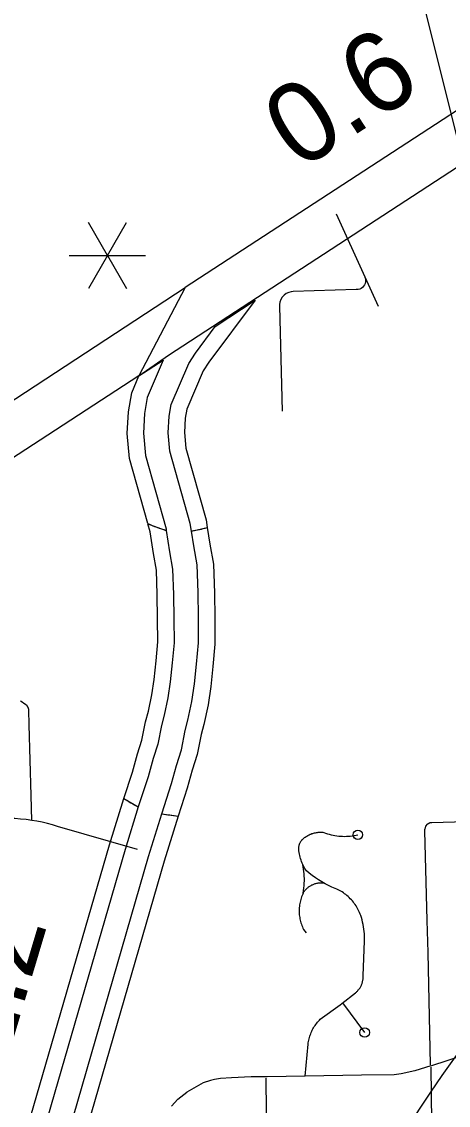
# Model space of a CAD drawing. Extents: x 309348 to 309445, y 336383 to 336484.
# Drawn here: x 309351.067 to 309351.516, y 336400.194 to 336401.336 of the extents above; entities that cross this region are included whole.
import ezdxf

# ---------------------------------------------------------------- set-up
doc = ezdxf.new("R2010")
doc.units = 0
doc.layers.add('R_Annotation', color=7, linetype='Continuous')

msp = doc.modelspace()

# ---------------------------------------------------------------- linework, layer by layer
at = {"layer": 'R_Annotation'}
for p, q in [((309351.1568, 336401.0896), (309351.1368, 336401.1242)), ((309351.1568, 336401.0896), (309351.1768, 336401.1242)), ((309351.1167, 336401.0896), (309351.1568, 336401.0896)), ((309351.1568, 336401.0896), (309351.1368, 336401.0549)), ((309351.1568, 336401.0896), (309351.1968, 336401.0896)), ((309351.1568, 336401.0896), (309351.1768, 336401.0549)), ((309351.2704, 336401.0147), (309351.3123, 336401.0426)), ((309351.1901, 336400.9626), (309351.2157, 336400.9791))]:
    msp.add_line(p, q, dxfattribs=at)
for points in [[(309351.7151, 336400.4543), (309351.2446, 336402.3368), (309349.4843, 336402.3368)], [(309353.5386, 336401.9502), (309353.1512, 336401.9259), (309352.6374, 336401.8975), (309352.6056, 336401.8933), (309352.5814, 336401.8881), (309352.5234, 336401.871), (309352.4797, 336401.8556), (309352.4295, 336401.8304), (309352.3881, 336401.8076), (309352.305, 336401.7552), (309352.2745, 336401.7342), (309351.6382, 336401.3162), (309351.2388, 336401.0557)], [(309351.2388, 336401.0557), (309351.1901, 336400.9626), (309351.2211, 336400.9844), (309351.6656, 336401.2744), (309352.3024, 336401.6927), (309352.3325, 336401.7134), (309352.4136, 336401.7645), (309352.4527, 336401.7861), (309352.4993, 336401.8094), (309352.5388, 336401.8234), (309352.5938, 336401.8396), (309352.6141, 336401.844), (309352.642, 336401.8477), (309353.1541, 336401.876), (309353.5417, 336401.9003)], [(309351.3978, 336401.1334), (309351.4278, 336401.067), (309351.428, 336401.0665), (309351.4285, 336401.0649), (309351.4286, 336401.0632), (309351.4285, 336401.0616), (309351.4281, 336401.06), (309351.4275, 336401.0585), (309351.4265, 336401.0571), (309351.4254, 336401.0559), (309351.4241, 336401.0549), (309351.4226, 336401.0542), (309351.421, 336401.0538), (309351.4194, 336401.0536), (309351.4188, 336401.0536), (309351.3525, 336401.0515), (309351.3505, 336401.0513), (309351.3478, 336401.0506), (309351.3452, 336401.0494), (309351.3429, 336401.0477), (309351.341, 336401.0456), (309351.3395, 336401.0432), (309351.3385, 336401.0405), (309351.3381, 336401.0377), (309351.338, 336401.0362), (309351.341, 336400.9255)], [(309351.4278, 336401.067), (309351.4418, 336401.0361)], [(309350.7477, 336400.7347), (309350.7689, 336400.7494), (309350.7971, 336400.7662), (309351.2388, 336401.0557), (309351.1901, 336400.9626)], [(309351.3123, 336401.0426), (309351.2635, 336400.9771), (309351.2577, 336400.9679), (309351.2404, 336400.9276), (309351.2387, 336400.9181), (309351.238, 336400.9029), (309351.2394, 336400.8864), (309351.2607, 336400.8108), (309351.262, 336400.8027)], [(309351.2453, 336400.7991), (309351.244, 336400.8072), (309351.2226, 336400.8833), (309351.2209, 336400.9026), (309351.2218, 336400.92), (309351.224, 336400.9325), (309351.2426, 336400.9758), (309351.2495, 336400.9867), (309351.2704, 336401.0147)], [(309351.2157, 336400.9791), (309351.1989, 336400.94), (309351.1959, 336400.9229), (309351.1948, 336400.9021), (309351.197, 336400.8786), (309351.2186, 336400.8015), (309351.2189, 336400.7998)], [(309351.1901, 336400.9626), (309350.8236, 336400.7238), (309350.796, 336400.7073), (309350.7757, 336400.6932)], [(309351.1994, 336400.8069), (309351.1802, 336400.8755), (309351.1778, 336400.9018), (309351.179, 336400.9248), (309351.1825, 336400.9449), (309351.1901, 336400.9626)], [(309351.1742, 336400.5173), (309351.1832, 336400.5448), (309351.1884, 336400.5641), (309351.1932, 336400.5788), (309351.197, 336400.598), (309351.2, 336400.6092), (309351.2036, 336400.6264), (309351.206, 336400.6426), (309351.2081, 336400.6622), (309351.21, 336400.6822), (309351.2097, 336400.7067), (309351.2094, 336400.7323), (309351.2085, 336400.7579), (309351.2053, 336400.7753), (309351.2019, 336400.7981), (309351.1995, 336400.8068)], [(309351.1995, 336400.8068), (309351.2052, 336400.8045), (309351.2189, 336400.7998)], [(309351.2189, 336400.7998), (309351.2223, 336400.7772), (309351.2255, 336400.7589), (309351.2265, 336400.7321), (309351.2268, 336400.7064), (309351.2271, 336400.6811), (309351.2251, 336400.6602), (309351.2231, 336400.6402), (309351.2205, 336400.6232), (309351.2167, 336400.6051), (309351.2138, 336400.5941), (309351.2099, 336400.5744), (309351.2049, 336400.5592), (309351.1997, 336400.5401), (309351.1893, 336400.5085)], [(309351.2142, 336400.5011), (309351.2243, 336400.5331), (309351.2295, 336400.5521), (309351.2348, 336400.5683), (309351.2388, 336400.5888), (309351.2417, 336400.5996), (309351.2459, 336400.6193), (309351.2486, 336400.6379), (309351.2508, 336400.6587), (309351.2529, 336400.6813), (309351.2526, 336400.7082), (309351.2523, 336400.7343), (309351.2512, 336400.7636), (309351.2477, 336400.7836), (309351.2453, 336400.7991)], [(309351.262, 336400.8027), (309351.2646, 336400.7851), (309351.2684, 336400.7643), (309351.2695, 336400.7337), (309351.2698, 336400.7075), (309351.2701, 336400.6798), (309351.2679, 336400.6563), (309351.2657, 336400.6351), (309351.2628, 336400.6158), (309351.2584, 336400.5952), (309351.2556, 336400.5845), (309351.2515, 336400.5636), (309351.246, 336400.5469), (309351.2409, 336400.528), (309351.2313, 336400.4986)], [(309351.2453, 336400.7991), (309351.262, 336400.8027)], [(309351.0773, 336400.4941), (309351.0765, 336400.5202), (309351.0746, 336400.5949), (309351.0741, 336400.6104), (309351.0741, 336400.6106), (309351.0741, 336400.6108), (309351.0741, 336400.611), (309351.074, 336400.6113), (309351.074, 336400.6115), (309351.0739, 336400.6117), (309351.0739, 336400.6119), (309351.0738, 336400.6121), (309351.0738, 336400.6123), (309351.0737, 336400.6125), (309351.0736, 336400.6127), (309351.0735, 336400.6129), (309351.0734, 336400.6131), (309351.0733, 336400.6133), (309351.0732, 336400.6135), (309351.0731, 336400.6137), (309351.073, 336400.6139), (309351.0728, 336400.6141), (309351.0727, 336400.6142), (309351.0726, 336400.6144), (309351.0724, 336400.6146), (309351.0723, 336400.6147), (309351.0706, 336400.6161), (309351.0688, 336400.6174), (309351.0671, 336400.6186), (309351.0653, 336400.6198)], [(309351.0727, 336399.4543), (309351.0557, 336399.4536), (309351.0515, 336399.4801), (309351.0657, 336399.5912), (309351.071, 336399.6624), (309351.0712, 336399.7171), (309351.0703, 336399.7842), (309351.0603, 336399.9436), (309351.0576, 336400.0443), (309351.0601, 336400.0883), (309351.0645, 336400.1326), (309351.0701, 336400.1608), (309351.1591, 336400.4684), (309351.1742, 336400.5173), (309351.1893, 336400.5085)], [(309351.1893, 336400.5085), (309351.1754, 336400.4635), (309351.0867, 336400.1568), (309351.0813, 336400.1301), (309351.0771, 336400.087), (309351.0746, 336400.0441), (309351.0773, 336399.9444), (309351.0873, 336399.7849), (309351.0882, 336399.7173), (309351.088, 336399.6617), (309351.0827, 336399.5895), (309351.0684, 336399.4788), (309351.0727, 336399.4543)], [(309351.2142, 336400.5011), (309351.2313, 336400.4986), (309351.2166, 336400.4512), (309351.1285, 336400.1465), (309351.1239, 336400.1237), (309351.1199, 336400.0836), (309351.1177, 336400.0434), (309351.1203, 336399.9463), (309351.1303, 336399.7865), (309351.1312, 336399.7179), (309351.131, 336399.6601), (309351.1255, 336399.5852), (309351.114, 336399.4958), (309351.1114, 336399.4754), (309351.1057, 336399.4547), (309351.0887, 336399.4547)], [(309351.0887, 336399.4547), (309351.0944, 336399.4767), (309351.0971, 336399.4979), (309351.1086, 336399.5869), (309351.114, 336399.6607), (309351.1142, 336399.7177), (309351.1133, 336399.7858), (309351.1033, 336399.9456), (309351.1006, 336400.0437), (309351.103, 336400.085), (309351.1071, 336400.1262), (309351.112, 336400.1506), (309351.2003, 336400.4561), (309351.2142, 336400.5011)], [(309351.0773, 336400.4941), (309351.0713, 336400.4949), (309351.0654, 336400.4955), (309351.0594, 336400.4959), (309351.0535, 336400.4961), (309351.0475, 336400.496), (309351.0298, 336400.4943)], [(309351.1884, 336400.4635), (309351.1044, 336400.4876), (309351.0991, 336400.4893), (309351.0937, 336400.4908), (309351.0882, 336400.4921), (309351.0827, 336400.4932), (309351.0773, 336400.4941)], [(309351.4936, 336400.3885), (309351.4912, 336400.4831), (309351.4912, 336400.4833), (309351.4912, 336400.4835), (309351.4912, 336400.4837), (309351.4912, 336400.4839), (309351.4912, 336400.4841), (309351.4912, 336400.4843), (309351.4912, 336400.4845), (309351.4912, 336400.4847), (309351.4913, 336400.4849), (309351.492, 336400.488), (309351.4939, 336400.4901)], [(309351.4939, 336400.4901), (309351.4941, 336400.4903), (309351.4942, 336400.4904), (309351.4944, 336400.4905), (309351.4945, 336400.4907), (309351.4947, 336400.4908), (309351.4948, 336400.4909), (309351.495, 336400.491), (309351.4951, 336400.4911), (309351.4953, 336400.4912), (309351.4955, 336400.4913), (309351.4957, 336400.4914), (309351.4958, 336400.4914), (309351.496, 336400.4915), (309351.4962, 336400.4916), (309351.4964, 336400.4916), (309351.4966, 336400.4917), (309351.4968, 336400.4917), (309351.4969, 336400.4918), (309351.4971, 336400.4918), (309351.4973, 336400.4919), (309351.4975, 336400.4919), (309351.4977, 336400.4919), (309351.4979, 336400.4919), (309351.4981, 336400.4919), (309351.4983, 336400.4919), (309351.5462, 336400.4931)], [(309351.3585, 336400.4619), (309351.3584, 336400.4635), (309351.3583, 336400.4651), (309351.3583, 336400.4657), (309351.3584, 336400.4662), (309351.3585, 336400.4667), (309351.3586, 336400.4672), (309351.3587, 336400.4677), (309351.3588, 336400.4682), (309351.359, 336400.4687), (309351.3592, 336400.4692), (309351.3594, 336400.4697), (309351.3596, 336400.4702), (309351.3598, 336400.4706), (309351.36, 336400.4711), (309351.3603, 336400.4716), (309351.3605, 336400.472), (309351.3608, 336400.4724), (309351.3611, 336400.4729), (309351.3614, 336400.4733), (309351.3617, 336400.4737), (309351.3621, 336400.4741), (309351.3628, 336400.4748), (309351.3636, 336400.4754), (309351.3644, 336400.476), (309351.3652, 336400.4765), (309351.366, 336400.4771), (309351.3668, 336400.4776), (309351.3677, 336400.4781), (309351.3685, 336400.4785), (309351.3694, 336400.479), (309351.3703, 336400.4794), (309351.3712, 336400.4797), (309351.3721, 336400.4801), (309351.3731, 336400.4804), (309351.374, 336400.4806), (309351.375, 336400.4809), (309351.3759, 336400.4811), (309351.3769, 336400.4812), (309351.3779, 336400.4814), (309351.3789, 336400.4815), (309351.3798, 336400.4815), (309351.3808, 336400.4816), (309351.3818, 336400.4816), (309351.3828, 336400.4815), (309351.3838, 336400.4815), (309351.3847, 336400.4814), (309351.3866, 336400.4807), (309351.3886, 336400.48), (309351.3905, 336400.4795), (309351.3925, 336400.4789), (309351.3945, 336400.4785), (309351.3964, 336400.4781), (309351.3984, 336400.4778), (309351.4005, 336400.4776), (309351.4025, 336400.4774), (309351.4045, 336400.4773), (309351.4065, 336400.4772), (309351.4086, 336400.4773), (309351.4106, 336400.4774), (309351.4126, 336400.4775), (309351.4146, 336400.4778), (309351.4166, 336400.4781), (309351.4186, 336400.4784), (309351.4206, 336400.4789)], [(309351.3625, 336400.4476), (309351.3618, 336400.4491), (309351.3612, 336400.4507), (309351.3607, 336400.4522), (309351.3602, 336400.4538), (309351.3597, 336400.4554), (309351.3594, 336400.457), (309351.359, 336400.4586), (309351.3587, 336400.4602), (309351.3585, 336400.4619)], [(309351.3629, 336400.4173), (309351.3636, 336400.4228), (309351.3639, 336400.4253), (309351.3641, 336400.4278), (309351.3642, 336400.4303), (309351.3642, 336400.4328), (309351.3641, 336400.4353), (309351.3639, 336400.4378), (309351.3637, 336400.4402), (309351.3634, 336400.4427), (309351.363, 336400.4452), (309351.3625, 336400.4476)], [(309351.3842, 336400.4284), (309351.3825, 336400.4293), (309351.3791, 336400.4314), (309351.3758, 336400.4336), (309351.3725, 336400.4359), (309351.3694, 336400.4383), (309351.3663, 336400.4409), (309351.3654, 336400.4422), (309351.3646, 336400.4435), (309351.3639, 336400.4449), (309351.3632, 336400.4462), (309351.3625, 336400.4476)], [(309351.3629, 336400.4173), (309351.3631, 336400.4176), (309351.3637, 336400.4189), (309351.3642, 336400.4195), (309351.3647, 336400.4201), (309351.3652, 336400.4207), (309351.3657, 336400.4213), (309351.3663, 336400.4219), (309351.3669, 336400.4224), (309351.3675, 336400.4229), (309351.3681, 336400.4234), (309351.3687, 336400.4239), (309351.3693, 336400.4244), (309351.37, 336400.4248), (309351.3706, 336400.4252), (309351.3713, 336400.4256), (309351.372, 336400.426), (309351.3727, 336400.4263), (309351.3734, 336400.4266), (309351.3742, 336400.4269), (309351.3749, 336400.4272), (309351.3757, 336400.4274), (309351.3764, 336400.4277), (309351.3772, 336400.4278), (309351.3779, 336400.428), (309351.3787, 336400.4281), (309351.3795, 336400.4283), (309351.3803, 336400.4283), (309351.381, 336400.4284), (309351.3818, 336400.4284), (309351.3826, 336400.4284), (309351.3834, 336400.4284), (309351.3842, 336400.4284)], [(309351.402, 336400.2998), (309351.4036, 336400.301), (309351.4179, 336400.3122), (309351.4184, 336400.3126), (309351.419, 336400.3131), (309351.4195, 336400.3136), (309351.4201, 336400.3142), (309351.4206, 336400.3147), (309351.421, 336400.3153), (309351.4215, 336400.3158), (309351.422, 336400.3164), (309351.4224, 336400.317), (309351.4228, 336400.3176), (309351.4232, 336400.3183), (309351.4235, 336400.3189), (309351.4239, 336400.3196), (309351.4242, 336400.3203), (309351.4245, 336400.3209), (309351.4248, 336400.3216), (309351.425, 336400.3223), (309351.4252, 336400.323), (309351.4254, 336400.3237), (309351.4256, 336400.3245), (309351.4258, 336400.3252), (309351.4259, 336400.3259), (309351.426, 336400.3266), (309351.4261, 336400.3274), (309351.4261, 336400.3281), (309351.4262, 336400.3289), (309351.4262, 336400.3296), (309351.4261, 336400.3303), (309351.4275, 336400.367), (309351.4276, 336400.3695), (309351.4275, 336400.372), (309351.4274, 336400.3745), (309351.4272, 336400.377), (309351.4269, 336400.3794), (309351.4266, 336400.3819), (309351.4261, 336400.3843), (309351.4256, 336400.3868), (309351.425, 336400.3892), (309351.4243, 336400.3916), (309351.4235, 336400.3939), (309351.423, 336400.3954), (309351.4224, 336400.3969), (309351.4217, 336400.3984), (309351.421, 336400.3998), (309351.4203, 336400.4012), (309351.4195, 336400.4026), (309351.4186, 336400.404), (309351.4177, 336400.4053), (309351.4168, 336400.4066), (309351.4158, 336400.4079), (309351.4148, 336400.4092), (309351.4137, 336400.4104), (309351.4126, 336400.4115), (309351.4115, 336400.4127), (309351.4103, 336400.4137), (309351.4091, 336400.4148), (309351.4079, 336400.4158), (309351.4066, 336400.4168), (309351.4053, 336400.4177), (309351.4039, 336400.4186), (309351.4025, 336400.4194), (309351.4011, 336400.4202), (309351.3997, 336400.4209), (309351.3983, 336400.4216), (309351.3968, 336400.4222), (309351.3931, 336400.4238), (309351.3895, 336400.4255), (309351.386, 336400.4273), (309351.3842, 336400.4284)], [(309351.3629, 336400.4173), (309351.3625, 336400.4163), (309351.3619, 336400.4149), (309351.3613, 336400.4135), (309351.3609, 336400.4121), (309351.3604, 336400.4107), (309351.36, 336400.4093), (309351.3597, 336400.4079), (309351.3594, 336400.4064), (309351.3592, 336400.405), (309351.359, 336400.4035), (309351.3588, 336400.402), (309351.3588, 336400.4006), (309351.3587, 336400.3991), (309351.3587, 336400.3976), (309351.3588, 336400.3961), (309351.3589, 336400.3947), (309351.3591, 336400.3932), (309351.3593, 336400.3918), (309351.3595, 336400.3903), (309351.3599, 336400.3889), (309351.3602, 336400.3874), (309351.3606, 336400.386), (309351.3611, 336400.3846), (309351.3616, 336400.3832), (309351.3621, 336400.3819), (309351.3627, 336400.3805), (309351.3634, 336400.3792), (309351.366, 336400.3754)], [(309351.4971, 336400.2365), (309351.4945, 336400.3548), (309351.4936, 336400.3885)], [(309351.4972, 336400.2352), (309351.5327, 336400.2471), (309351.5631, 336400.2583), (309351.5827, 336400.2659), (309351.6156, 336400.2798), (309351.6433, 336400.293), (309351.6605, 336400.3043), (309351.6668, 336400.3094), (309351.6753, 336400.3167)], [(309351.365, 336400.2246), (309351.3683, 336400.2581), (309351.3684, 336400.2596), (309351.3686, 336400.261), (309351.3689, 336400.2624), (309351.3692, 336400.2637), (309351.3696, 336400.2651), (309351.37, 336400.2665), (309351.3704, 336400.2678), (309351.3709, 336400.2692), (309351.3714, 336400.2705), (309351.372, 336400.2718), (309351.3726, 336400.2731), (309351.3733, 336400.2743), (309351.374, 336400.2755), (309351.3747, 336400.2768), (309351.3755, 336400.2779), (309351.3764, 336400.2791), (309351.3772, 336400.2802), (309351.3781, 336400.2813), (309351.3791, 336400.2824), (309351.38, 336400.2834), (309351.381, 336400.2844), (309351.402, 336400.2998)], [(309351.4045, 336400.3017), (309351.4277, 336400.2705)], [(309351.4972, 336400.2352), (309351.4805, 336400.2301), (309351.4662, 336400.2268), (309351.4586, 336400.2259), (309351.4244, 336400.2255), (309351.365, 336400.2246), (309351.3252, 336400.2238), (309351.3081, 336400.2238), (309351.2875, 336400.2228), (309351.2759, 336400.2219), (309351.2696, 336400.2211), (309351.2655, 336400.22), (309351.2577, 336400.2173), (309351.2405, 336400.2075)], [(309351.4972, 336400.2338), (309351.4985, 336400.147), (309351.4982, 336400.1064)], [(309351.3237, 336400.2223), (309351.3243, 336400.151), (309351.3254, 336400.0959), (309351.3269, 336400.0591), (309351.3262, 336400.012), (309351.3263, 336399.9995), (309351.3263, 336399.9991), (309351.3264, 336399.9987), (309351.3264, 336399.9983), (309351.3265, 336399.998), (309351.3266, 336399.9976), (309351.3267, 336399.9973), (309351.3268, 336399.9969), (309351.3269, 336399.9965), (309351.327, 336399.9962), (309351.3271, 336399.9958), (309351.3273, 336399.9955), (309351.3274, 336399.9952), (309351.3276, 336399.9948), (309351.3278, 336399.9945), (309351.328, 336399.9942), (309351.3282, 336399.9939), (309351.3284, 336399.9936), (309351.3285, 336399.9935)], [(309351.2242, 336400.1929), (309351.2309, 336400.2002), (309351.2405, 336400.2075)]]:
    msp.add_lwpolyline(points, dxfattribs=at)
for centre in [(309351.4206, 336400.4789), (309351.4277, 336400.2705)]:
    msp.add_circle(centre, 0.005, dxfattribs=at)
for centre, radius, start, end in [((309351.2541, 336400.9274), 0.1323, 245.578, 254.5407), ((309351.2541, 336400.9274), 0.1323, 245.578, 254.5407), ((309351.2128, 336400.9923), 0.1959, 279.5618, 284.542), ((309351.2128, 336400.9923), 0.1959, 279.5618, 284.542), ((309351.2437, 336400.6181), 0.1224, 235.4254, 243.6106), ((309351.2437, 336400.6181), 0.1224, 235.4254, 243.6106), ((309351.3732, 336401.5463), 1.0573, 261.3515, 262.2846), ((309351.3732, 336401.5463), 1.0573, 261.3515, 262.2846)]:
    msp.add_arc(centre, radius, start, end, dxfattribs=at)
msp.add_ellipse((309351.9438, 336399.908), major_axis=(-0.4621, -0.6892), ratio=0.64799, dxfattribs=at)

# ---------------------------------------------------------------- texts
for s, rotation, p in [('0.6', 33.1144, (309351.3588, 336401.1782)), ('2.2', 73.3856, (309351.049, 336400.2341))]:
    msp.add_text(s, height=0.08451, rotation=rotation, dxfattribs=at).set_placement(p)

doc.saveas('drawing.dxf')
